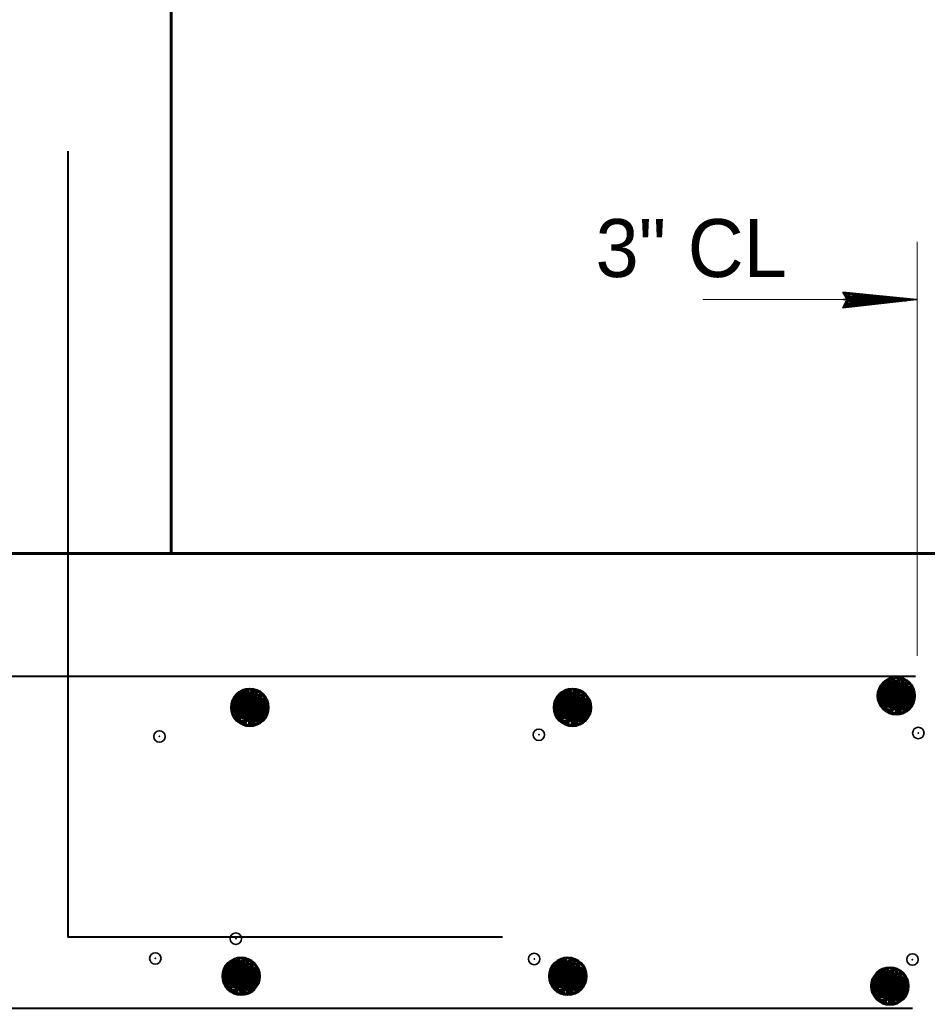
# Model space of a CAD drawing. Extents: x 4.49 to 7.69, y 0.28 to 2.27.
# Drawn here: x 6.0882 to 6.2187, y 1.4319 to 1.5741 of the extents above; entities that cross this region are included whole.
import ezdxf

# ---------------------------------------------------------------- set-up
doc = ezdxf.new("R2010")
doc.units = 0
doc.header["$LTSCALE"] = 0.0033
doc.header["$PDMODE"] = 32
doc.header["$PDSIZE"] = 0.00165
doc.layers.add('1', color=7, linetype='Continuous', lineweight=35)

msp = doc.modelspace()

# ---------------------------------------------------------------- linework, layer by layer
at = {"layer": '1', "lineweight": 13}
for p, q in [((6.21725, 1.482583), (6.21725, 1.542167)), ((6.186417, 1.533833), (6.20725, 1.533833))]:
    msp.add_line(p, q, dxfattribs=at)
at = {"layer": '1'}
for p, q in [((6.206833, 1.534833), (6.214667, 1.533917)), ((6.206833, 1.534833), (6.214667, 1.533917)), ((6.206833, 1.53475), (6.214667, 1.533917)), ((6.206833, 1.534667), (6.214667, 1.533833)), ((6.206833, 1.534667), (6.214667, 1.533667)), ((6.206583, 1.533833), (6.217167, 1.533833)), ((6.20675, 1.533167), (6.214083, 1.533917)), ((6.206833, 1.533), (6.214167, 1.533833)), ((6.206833, 1.532917), (6.214167, 1.533667)), ((6.206833, 1.53275), (6.214167, 1.533583))]:
    msp.add_line(p, q, dxfattribs=at)
at = {"layer": '1', "lineweight": 40}
for p, q in [((5.836083, 1.479667), (6.217, 1.479667)), ((6.212583, 1.47875), (6.216417, 1.478083)), ((6.2145, 1.477917), (6.215833, 1.478917)), ((6.216583, 1.478083), (6.215333, 1.47925)), ((6.1215, 1.47625), (6.122833, 1.47725)), ((6.123583, 1.476417), (6.122333, 1.477583)), ((6.167917, 1.47625), (6.16925, 1.47725)), ((6.17, 1.476417), (6.16875, 1.477583)), ((6.212167, 1.478417), (6.21675, 1.47625)), ((6.212333, 1.477417), (6.216167, 1.47675)), ((6.212333, 1.47725), (6.216167, 1.4765)), ((6.212417, 1.478), (6.216333, 1.47725)), ((6.212417, 1.477833), (6.216333, 1.477083)), ((6.212417, 1.477583), (6.21625, 1.476833)), ((6.2125, 1.478417), (6.216417, 1.47775)), ((6.2125, 1.47825), (6.216417, 1.4775)), ((6.119167, 1.47675), (6.12375, 1.474583)), ((6.119333, 1.47575), (6.123167, 1.475083)), ((6.119417, 1.476333), (6.123333, 1.475583)), ((6.119417, 1.476167), (6.123333, 1.475417)), ((6.119417, 1.475917), (6.12325, 1.475167)), ((6.1195, 1.47675), (6.123417, 1.476083)), ((6.1195, 1.476583), (6.123417, 1.475833)), ((6.119583, 1.477083), (6.123417, 1.476417)), ((6.165583, 1.47675), (6.170167, 1.474583)), ((6.16575, 1.47575), (6.169583, 1.475083)), ((6.165833, 1.476333), (6.16975, 1.475583)), ((6.165833, 1.476167), (6.16975, 1.475417)), ((6.165833, 1.475917), (6.169667, 1.475167)), ((6.165917, 1.47675), (6.169833, 1.476083)), ((6.165917, 1.476583), (6.169833, 1.475833)), ((6.166, 1.477083), (6.169833, 1.476417)), ((6.212083, 1.476167), (6.216, 1.475417)), ((6.212083, 1.476), (6.215917, 1.47525)), ((6.212083, 1.47575), (6.215917, 1.475083)), ((6.212167, 1.476583), (6.216083, 1.475833)), ((6.21225, 1.477), (6.216083, 1.47625)), ((6.21225, 1.476833), (6.216083, 1.476083)), ((6.119083, 1.4745), (6.123, 1.47375)), ((6.119083, 1.474333), (6.122917, 1.473583)), ((6.119167, 1.474917), (6.123083, 1.474167)), ((6.11925, 1.475333), (6.123083, 1.474583)), ((6.11925, 1.475167), (6.123083, 1.474417)), ((6.119333, 1.475583), (6.123167, 1.474833)), ((6.1655, 1.4745), (6.169417, 1.47375)), ((6.1655, 1.474333), (6.169333, 1.473583)), ((6.165583, 1.474917), (6.1695, 1.474167)), ((6.165667, 1.475333), (6.1695, 1.474583)), ((6.165667, 1.475167), (6.1695, 1.474417)), ((6.16575, 1.475583), (6.169583, 1.474833)), ((6.212, 1.475667), (6.215833, 1.474917)), ((6.212, 1.4755), (6.215833, 1.47475)), ((6.216333, 1.47525), (6.212583, 1.474833)), ((6.119, 1.474), (6.122833, 1.47325)), ((6.119, 1.473833), (6.122833, 1.473083)), ((6.119083, 1.474083), (6.122917, 1.473417)), ((6.123333, 1.473583), (6.119583, 1.473167)), ((6.165417, 1.474), (6.16925, 1.47325)), ((6.165417, 1.473833), (6.16925, 1.473083)), ((6.1655, 1.474083), (6.169333, 1.473417)), ((6.16975, 1.473583), (6.166, 1.473167)), ((6.122333, 1.43775), (6.121083, 1.438917)), ((6.169333, 1.43775), (6.168083, 1.438917)), ((6.117917, 1.438083), (6.1225, 1.435917)), ((6.118167, 1.437667), (6.122083, 1.436917)), ((6.118167, 1.4375), (6.122083, 1.43675)), ((6.11825, 1.438083), (6.122167, 1.437417)), ((6.11825, 1.437917), (6.122167, 1.437167)), ((6.118333, 1.438417), (6.122167, 1.43775)), ((6.12025, 1.437583), (6.121583, 1.438583)), ((6.164917, 1.438083), (6.1695, 1.435917)), ((6.165167, 1.437667), (6.169083, 1.436917)), ((6.165167, 1.4375), (6.169083, 1.43675)), ((6.16525, 1.438083), (6.169167, 1.437417)), ((6.16525, 1.437917), (6.169167, 1.437167)), ((6.165333, 1.438417), (6.169167, 1.43775)), ((6.16725, 1.437583), (6.168583, 1.438583)), ((6.215667, 1.436333), (6.214417, 1.4375)), ((6.117917, 1.43625), (6.121833, 1.4355)), ((6.118, 1.436667), (6.121833, 1.435917)), ((6.118, 1.4365), (6.121833, 1.43575)), ((6.118083, 1.437083), (6.121917, 1.436417)), ((6.118083, 1.436917), (6.121917, 1.436167)), ((6.118167, 1.43725), (6.122, 1.4365)), ((6.164917, 1.43625), (6.168833, 1.4355)), ((6.165, 1.436667), (6.168833, 1.435917)), ((6.165, 1.4365), (6.168833, 1.43575)), ((6.165083, 1.437083), (6.168917, 1.436417)), ((6.165083, 1.436917), (6.168917, 1.436167)), ((6.165167, 1.43725), (6.169, 1.4365)), ((6.21125, 1.436667), (6.215833, 1.4345)), ((6.2115, 1.43625), (6.215417, 1.4355)), ((6.2115, 1.436083), (6.215417, 1.435333)), ((6.211583, 1.436667), (6.2155, 1.436)), ((6.211583, 1.4365), (6.2155, 1.43575)), ((6.211667, 1.437), (6.2155, 1.436333)), ((6.213583, 1.436167), (6.214917, 1.437167)), ((6.11775, 1.435333), (6.121583, 1.434583)), ((6.11775, 1.435167), (6.121583, 1.434417)), ((6.117833, 1.435833), (6.12175, 1.435083)), ((6.117833, 1.435667), (6.121667, 1.434917)), ((6.117833, 1.435417), (6.121667, 1.43475)), ((6.122083, 1.434917), (6.118333, 1.4345)), ((6.16475, 1.435333), (6.168583, 1.434583)), ((6.16475, 1.435167), (6.168583, 1.434417)), ((6.164833, 1.435833), (6.16875, 1.435083)), ((6.164833, 1.435667), (6.168667, 1.434917)), ((6.164833, 1.435417), (6.168667, 1.43475)), ((6.169083, 1.434917), (6.165333, 1.4345)), ((6.21125, 1.434833), (6.215167, 1.434083)), ((6.211333, 1.43525), (6.215167, 1.4345)), ((6.211333, 1.435083), (6.215167, 1.434333)), ((6.211417, 1.435667), (6.21525, 1.435)), ((6.211417, 1.4355), (6.21525, 1.43475)), ((6.2115, 1.435833), (6.215333, 1.435083)), ((6.211083, 1.433917), (6.214917, 1.433167)), ((6.211083, 1.43375), (6.214917, 1.433)), ((6.211167, 1.434417), (6.215083, 1.433667)), ((6.211167, 1.43425), (6.215, 1.4335)), ((6.211167, 1.434), (6.215, 1.433333)), ((6.215417, 1.4335), (6.211667, 1.433083)), ((5.836083, 1.431917), (6.216583, 1.431917))]:
    msp.add_line(p, q, dxfattribs=at)
at = {"layer": '1', "lineweight": 60}
for p, q in [((6.212417, 1.478417), (6.21225, 1.4755)), ((6.212667, 1.478417), (6.212417, 1.4755)), ((6.212833, 1.478417), (6.212667, 1.475417)), ((6.213, 1.478417), (6.21275, 1.475417)), ((6.213167, 1.478417), (6.213, 1.475417)), ((6.213417, 1.478417), (6.21325, 1.475417)), ((6.213667, 1.478417), (6.213417, 1.475417)), ((6.21375, 1.478333), (6.213583, 1.475417)), ((6.213917, 1.478333), (6.21375, 1.475417)), ((6.214083, 1.478333), (6.213917, 1.475417)), ((6.214333, 1.478333), (6.214083, 1.475417)), ((6.2145, 1.478333), (6.214333, 1.475417)), ((6.21475, 1.47825), (6.2145, 1.475333)), ((6.215, 1.47825), (6.21475, 1.475333)), ((6.215167, 1.47825), (6.215, 1.475333)), ((6.21525, 1.47825), (6.215083, 1.475333)), ((6.215417, 1.47825), (6.21525, 1.475333)), ((6.2155, 1.47825), (6.215333, 1.475333)), ((6.21575, 1.478167), (6.2155, 1.47525)), ((6.215917, 1.478167), (6.21575, 1.47525)), ((6.216083, 1.478167), (6.215833, 1.47525)), ((6.21625, 1.478167), (6.216083, 1.47525)), ((6.2165, 1.478167), (6.216333, 1.47525)), ((6.21675, 1.47625), (6.216583, 1.478083)), ((6.119417, 1.47675), (6.11925, 1.473833)), ((6.119667, 1.47675), (6.119417, 1.473833)), ((6.119833, 1.47675), (6.119667, 1.47375)), ((6.12, 1.47675), (6.11975, 1.47375)), ((6.120167, 1.47675), (6.12, 1.47375)), ((6.120417, 1.47675), (6.12025, 1.47375)), ((6.120667, 1.47675), (6.120417, 1.47375)), ((6.12075, 1.476667), (6.120583, 1.47375)), ((6.120917, 1.476667), (6.12075, 1.47375)), ((6.121083, 1.476667), (6.120917, 1.47375)), ((6.121333, 1.476667), (6.121083, 1.47375)), ((6.1215, 1.476667), (6.121333, 1.47375)), ((6.12175, 1.476583), (6.1215, 1.473667)), ((6.122, 1.476583), (6.12175, 1.473667)), ((6.122167, 1.476583), (6.122, 1.473667)), ((6.12225, 1.476583), (6.122083, 1.473667)), ((6.122417, 1.476583), (6.12225, 1.473667)), ((6.1225, 1.476583), (6.122333, 1.473667)), ((6.12275, 1.4765), (6.1225, 1.473583)), ((6.122917, 1.4765), (6.12275, 1.473583)), ((6.123083, 1.4765), (6.122833, 1.473583)), ((6.12325, 1.4765), (6.123083, 1.473583)), ((6.1235, 1.4765), (6.123333, 1.473583)), ((6.12375, 1.474583), (6.123583, 1.476417)), ((6.165833, 1.47675), (6.165667, 1.473833)), ((6.166083, 1.47675), (6.165833, 1.473833)), ((6.16625, 1.47675), (6.166083, 1.47375)), ((6.166417, 1.47675), (6.166167, 1.47375)), ((6.166583, 1.47675), (6.166417, 1.47375)), ((6.166833, 1.47675), (6.166667, 1.47375)), ((6.167083, 1.47675), (6.166833, 1.47375)), ((6.167167, 1.476667), (6.167, 1.47375)), ((6.167333, 1.476667), (6.167167, 1.47375)), ((6.1675, 1.476667), (6.167333, 1.47375)), ((6.16775, 1.476667), (6.1675, 1.47375)), ((6.167917, 1.476667), (6.16775, 1.47375)), ((6.168167, 1.476583), (6.167917, 1.473667)), ((6.168417, 1.476583), (6.168167, 1.473667)), ((6.168583, 1.476583), (6.168417, 1.473667)), ((6.168667, 1.476583), (6.1685, 1.473667)), ((6.168833, 1.476583), (6.168667, 1.473667)), ((6.168917, 1.476583), (6.16875, 1.473667)), ((6.169167, 1.4765), (6.168917, 1.473583)), ((6.169333, 1.4765), (6.169167, 1.473583)), ((6.1695, 1.4765), (6.16925, 1.473583)), ((6.169667, 1.4765), (6.1695, 1.473583)), ((6.169917, 1.4765), (6.16975, 1.473583)), ((6.170167, 1.474583), (6.17, 1.476417)), ((6.21675, 1.47625), (6.212, 1.4755)), ((6.12375, 1.474583), (6.119, 1.473833)), ((6.170167, 1.474583), (6.165417, 1.473833)), ((6.118167, 1.438083), (6.118, 1.435167)), ((6.118417, 1.438083), (6.118167, 1.435167)), ((6.118583, 1.438083), (6.118417, 1.435083)), ((6.11875, 1.438083), (6.1185, 1.435083)), ((6.118917, 1.438083), (6.11875, 1.435083)), ((6.119167, 1.438083), (6.119, 1.435083)), ((6.119417, 1.438083), (6.119167, 1.435083)), ((6.1195, 1.438), (6.119333, 1.435083)), ((6.119667, 1.438), (6.1195, 1.435083)), ((6.119833, 1.438), (6.119667, 1.435083)), ((6.120083, 1.438), (6.119833, 1.435083)), ((6.12025, 1.438), (6.120083, 1.435083)), ((6.1205, 1.437917), (6.12025, 1.435)), ((6.12075, 1.437917), (6.1205, 1.435)), ((6.120917, 1.437917), (6.12075, 1.435)), ((6.121, 1.437917), (6.120833, 1.435)), ((6.121167, 1.437917), (6.121, 1.435)), ((6.12125, 1.437917), (6.121083, 1.435)), ((6.1215, 1.437833), (6.12125, 1.434917)), ((6.121667, 1.437833), (6.1215, 1.434917)), ((6.121833, 1.437833), (6.121583, 1.434917)), ((6.122, 1.437833), (6.121833, 1.434917)), ((6.12225, 1.437833), (6.122083, 1.434917)), ((6.1225, 1.435917), (6.122333, 1.43775)), ((6.165167, 1.438083), (6.165, 1.435167)), ((6.165417, 1.438083), (6.165167, 1.435167)), ((6.165583, 1.438083), (6.165417, 1.435083)), ((6.16575, 1.438083), (6.1655, 1.435083)), ((6.165917, 1.438083), (6.16575, 1.435083)), ((6.166167, 1.438083), (6.166, 1.435083)), ((6.166417, 1.438083), (6.166167, 1.435083)), ((6.1665, 1.438), (6.166333, 1.435083)), ((6.166667, 1.438), (6.1665, 1.435083)), ((6.166833, 1.438), (6.166667, 1.435083)), ((6.167083, 1.438), (6.166833, 1.435083)), ((6.16725, 1.438), (6.167083, 1.435083)), ((6.1675, 1.437917), (6.16725, 1.435)), ((6.16775, 1.437917), (6.1675, 1.435)), ((6.167917, 1.437917), (6.16775, 1.435)), ((6.168, 1.437917), (6.167833, 1.435)), ((6.168167, 1.437917), (6.168, 1.435)), ((6.16825, 1.437917), (6.168083, 1.435)), ((6.1685, 1.437833), (6.16825, 1.434917)), ((6.168667, 1.437833), (6.1685, 1.434917)), ((6.168833, 1.437833), (6.168583, 1.434917)), ((6.169, 1.437833), (6.168833, 1.434917)), ((6.16925, 1.437833), (6.169083, 1.434917)), ((6.1695, 1.435917), (6.169333, 1.43775)), ((6.1225, 1.435917), (6.11775, 1.435167)), ((6.1695, 1.435917), (6.16475, 1.435167)), ((6.2115, 1.436667), (6.211333, 1.43375)), ((6.21175, 1.436667), (6.2115, 1.43375)), ((6.211917, 1.436667), (6.21175, 1.433667)), ((6.212083, 1.436667), (6.211833, 1.433667)), ((6.21225, 1.436667), (6.212083, 1.433667)), ((6.2125, 1.436667), (6.212333, 1.433667)), ((6.21275, 1.436667), (6.2125, 1.433667)), ((6.212833, 1.436583), (6.212667, 1.433667)), ((6.213, 1.436583), (6.212833, 1.433667)), ((6.213167, 1.436583), (6.213, 1.433667)), ((6.213417, 1.436583), (6.213167, 1.433667)), ((6.213583, 1.436583), (6.213417, 1.433667)), ((6.213833, 1.4365), (6.213583, 1.433583)), ((6.214083, 1.4365), (6.213833, 1.433583)), ((6.21425, 1.4365), (6.214083, 1.433583)), ((6.214333, 1.4365), (6.214167, 1.433583)), ((6.2145, 1.4365), (6.214333, 1.433583)), ((6.214583, 1.4365), (6.214417, 1.433583)), ((6.214833, 1.436417), (6.214583, 1.4335)), ((6.215, 1.436417), (6.214833, 1.4335)), ((6.215167, 1.436417), (6.214917, 1.4335)), ((6.215333, 1.436417), (6.215167, 1.4335)), ((6.215583, 1.436417), (6.215417, 1.4335)), ((6.215833, 1.4345), (6.215667, 1.436333)), ((6.215833, 1.4345), (6.211083, 1.43375))]:
    msp.add_line(p, q, dxfattribs=at)
for points in [[(6.109917, 1.6015), (6.109917, 1.497333), (6.234917, 1.497333)], [(5.94325, 1.497333), (6.00575, 1.497333), (6.00575, 1.518167), (6.047417, 1.518167), (6.047417, 1.497333), (6.109917, 1.497333)], [(6.215833, 1.47475), (6.215833, 1.478917), (6.214167, 1.47425), (6.214667, 1.479417), (6.212583, 1.474833), (6.213333, 1.479333), (6.214917, 1.474333), (6.21175, 1.477667), (6.216583, 1.478083), (6.213333, 1.474417), (6.215333, 1.47925), (6.212167, 1.478417), (6.212, 1.4755)], [(6.212583, 1.474833), (6.214083, 1.477083), (6.211917, 1.478), (6.213917, 1.479417), (6.214083, 1.477167), (6.21575, 1.474833), (6.21175, 1.477167), (6.2145, 1.477917)], [(6.215333, 1.47925), (6.214083, 1.477083), (6.216333, 1.47525)], [(6.122833, 1.473083), (6.122833, 1.47725), (6.121167, 1.472583), (6.121667, 1.47775), (6.119583, 1.473167), (6.120333, 1.477667), (6.121917, 1.472667), (6.11875, 1.476), (6.123583, 1.476417), (6.120333, 1.47275), (6.122333, 1.477583), (6.119167, 1.47675), (6.119, 1.473833)], [(6.119583, 1.473167), (6.121083, 1.475417), (6.118917, 1.476333), (6.120917, 1.47775), (6.121083, 1.4755), (6.12275, 1.473167), (6.11875, 1.4755), (6.1215, 1.47625)], [(6.122333, 1.477583), (6.121083, 1.475417), (6.123333, 1.473583)], [(6.16925, 1.473083), (6.16925, 1.47725), (6.167583, 1.472583), (6.168083, 1.47775), (6.166, 1.473167), (6.16675, 1.477667), (6.168333, 1.472667), (6.165167, 1.476), (6.17, 1.476417), (6.16675, 1.47275), (6.16875, 1.477583), (6.165583, 1.47675), (6.165417, 1.473833)], [(6.166, 1.473167), (6.1675, 1.475417), (6.165333, 1.476333), (6.167333, 1.47775), (6.1675, 1.4755), (6.169167, 1.473167), (6.165167, 1.4755), (6.167917, 1.47625)], [(6.16875, 1.477583), (6.1675, 1.475417), (6.16975, 1.473583)], [(6.211583, 1.47675), (6.21675, 1.477417), (6.212167, 1.478417)], [(6.118583, 1.475083), (6.12375, 1.47575), (6.119167, 1.47675)], [(6.165, 1.475083), (6.170167, 1.47575), (6.165583, 1.47675)], [(6.121583, 1.434417), (6.121583, 1.438583), (6.119917, 1.433917), (6.120417, 1.439083), (6.118333, 1.4345), (6.119083, 1.439), (6.120667, 1.434), (6.1175, 1.437333), (6.122333, 1.43775), (6.119083, 1.434083), (6.121083, 1.438917), (6.117917, 1.438083), (6.11775, 1.435167)], [(6.118333, 1.4345), (6.119833, 1.43675), (6.117667, 1.437667), (6.119667, 1.439083), (6.119833, 1.436833), (6.1215, 1.4345), (6.1175, 1.436833), (6.12025, 1.437583)], [(6.121083, 1.438917), (6.119833, 1.43675), (6.122083, 1.434917)], [(6.168583, 1.434417), (6.168583, 1.438583), (6.166917, 1.433917), (6.167417, 1.439083), (6.165333, 1.4345), (6.166083, 1.439), (6.167667, 1.434), (6.1645, 1.437333), (6.169333, 1.43775), (6.166083, 1.434083), (6.168083, 1.438917), (6.164917, 1.438083), (6.16475, 1.435167)], [(6.165333, 1.4345), (6.166833, 1.43675), (6.164667, 1.437667), (6.166667, 1.439083), (6.166833, 1.436833), (6.1685, 1.4345), (6.1645, 1.436833), (6.16725, 1.437583)], [(6.168083, 1.438917), (6.166833, 1.43675), (6.169083, 1.434917)], [(6.117333, 1.436417), (6.1225, 1.437083), (6.117917, 1.438083)], [(6.164333, 1.436417), (6.1695, 1.437083), (6.164917, 1.438083)], [(6.214917, 1.433), (6.214917, 1.437167), (6.21325, 1.4325), (6.21375, 1.437667), (6.211667, 1.433083), (6.212417, 1.437583), (6.214, 1.432583), (6.210833, 1.435917), (6.215667, 1.436333), (6.212417, 1.432667), (6.214417, 1.4375), (6.21125, 1.436667), (6.211083, 1.43375)], [(6.211667, 1.433083), (6.213167, 1.435333), (6.211, 1.43625), (6.213, 1.437667), (6.213167, 1.435417), (6.214833, 1.433083), (6.210833, 1.435417), (6.213583, 1.436167)], [(6.214417, 1.4375), (6.213167, 1.435333), (6.215417, 1.4335)], [(6.210667, 1.435), (6.215833, 1.435667), (6.21125, 1.436667)]]:
    msp.add_lwpolyline(points, dxfattribs=at)
at = {"layer": '1', "lineweight": 40}
for points in [[(6.095083, 1.555167), (6.095083, 1.442167), (6.157583, 1.442167)], [(6.212, 1.4755), (6.214083, 1.47425), (6.215833, 1.47475), (6.21675, 1.47625)], [(6.119, 1.473833), (6.121083, 1.472583), (6.122833, 1.473083), (6.12375, 1.474583)], [(6.165417, 1.473833), (6.1675, 1.472583), (6.16925, 1.473083), (6.170167, 1.474583)], [(6.11775, 1.435167), (6.119833, 1.433917), (6.121583, 1.434417), (6.1225, 1.435917)], [(6.16475, 1.435167), (6.166833, 1.433917), (6.168583, 1.434417), (6.1695, 1.435917)], [(6.211083, 1.43375), (6.213167, 1.4325), (6.214917, 1.433), (6.215833, 1.4345)]]:
    msp.add_lwpolyline(points, dxfattribs=at)
at = {"layer": '1'}
for points in [[(6.206583, 1.534917), (6.217167, 1.533833), (6.206583, 1.532667), (6.207167, 1.533833)], [(6.207333, 1.533917), (6.212, 1.534), (6.212, 1.533917), (6.211083, 1.533917), (6.207333, 1.534), (6.210333, 1.534083), (6.207167, 1.534167), (6.209417, 1.53425), (6.207167, 1.534333), (6.210667, 1.534083), (6.215333, 1.533917), (6.214417, 1.533667), (6.215667, 1.533667), (6.207333, 1.533667), (6.20975, 1.5335), (6.207167, 1.5335), (6.2125, 1.533917), (6.207167, 1.53325)]]:
    msp.add_lwpolyline(points, close=True, dxfattribs=at)
msp.add_lwpolyline([(6.207333, 1.533917), (6.206917, 1.534667), (6.207167, 1.534417), (6.207333, 1.534083), (6.207583, 1.534167), (6.207417, 1.5345), (6.20725, 1.53375), (6.207083, 1.53325), (6.206833, 1.532833)], dxfattribs=at)
at = {"layer": '1', "lineweight": 60}
for centre in [(6.21425, 1.47685), (6.12125, 1.475183), (6.167667, 1.475183), (6.12, 1.436517), (6.167, 1.436517), (6.213333, 1.4351)]:
    msp.add_circle(centre, 0.00264, dxfattribs=at)
at = {"layer": '1'}
for p in [(6.1205, 1.47575), (6.1675, 1.475917), (6.214583, 1.476083), (6.10825, 1.471), (6.162833, 1.47125), (6.217417, 1.4715), (6.11925, 1.441917), (6.107667, 1.439083), (6.162167, 1.439), (6.216583, 1.438917), (6.120083, 1.435167), (6.167083, 1.435167), (6.214083, 1.435167)]:
    msp.add_point(p, dxfattribs=at)

# ---------------------------------------------------------------- texts
msp.add_text('3" CL', height=0.008334, dxfattribs=at).set_placement((6.171, 1.537083))

doc.saveas('drawing.dxf')
